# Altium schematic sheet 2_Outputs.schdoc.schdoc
size 309 x 223 mm; Symbol: Sheet-Symbol_A4; Device: Sheet-Symbol_A4; Company: Velizy Astro Club; Drawed: Paul V.; Reviewed: Denis G.; Version: V1.0; Page Size: A4; @Project Name: NAFA AstrAlim; @Page Count: 2; @Update Date: 2024-01-05; @Create Date: 2023-12-28; @Schematic Name: AstrAlim NAFA; Part Number: AstrAlim-v1.0; @Page No: 2; @Page Name: Outputs
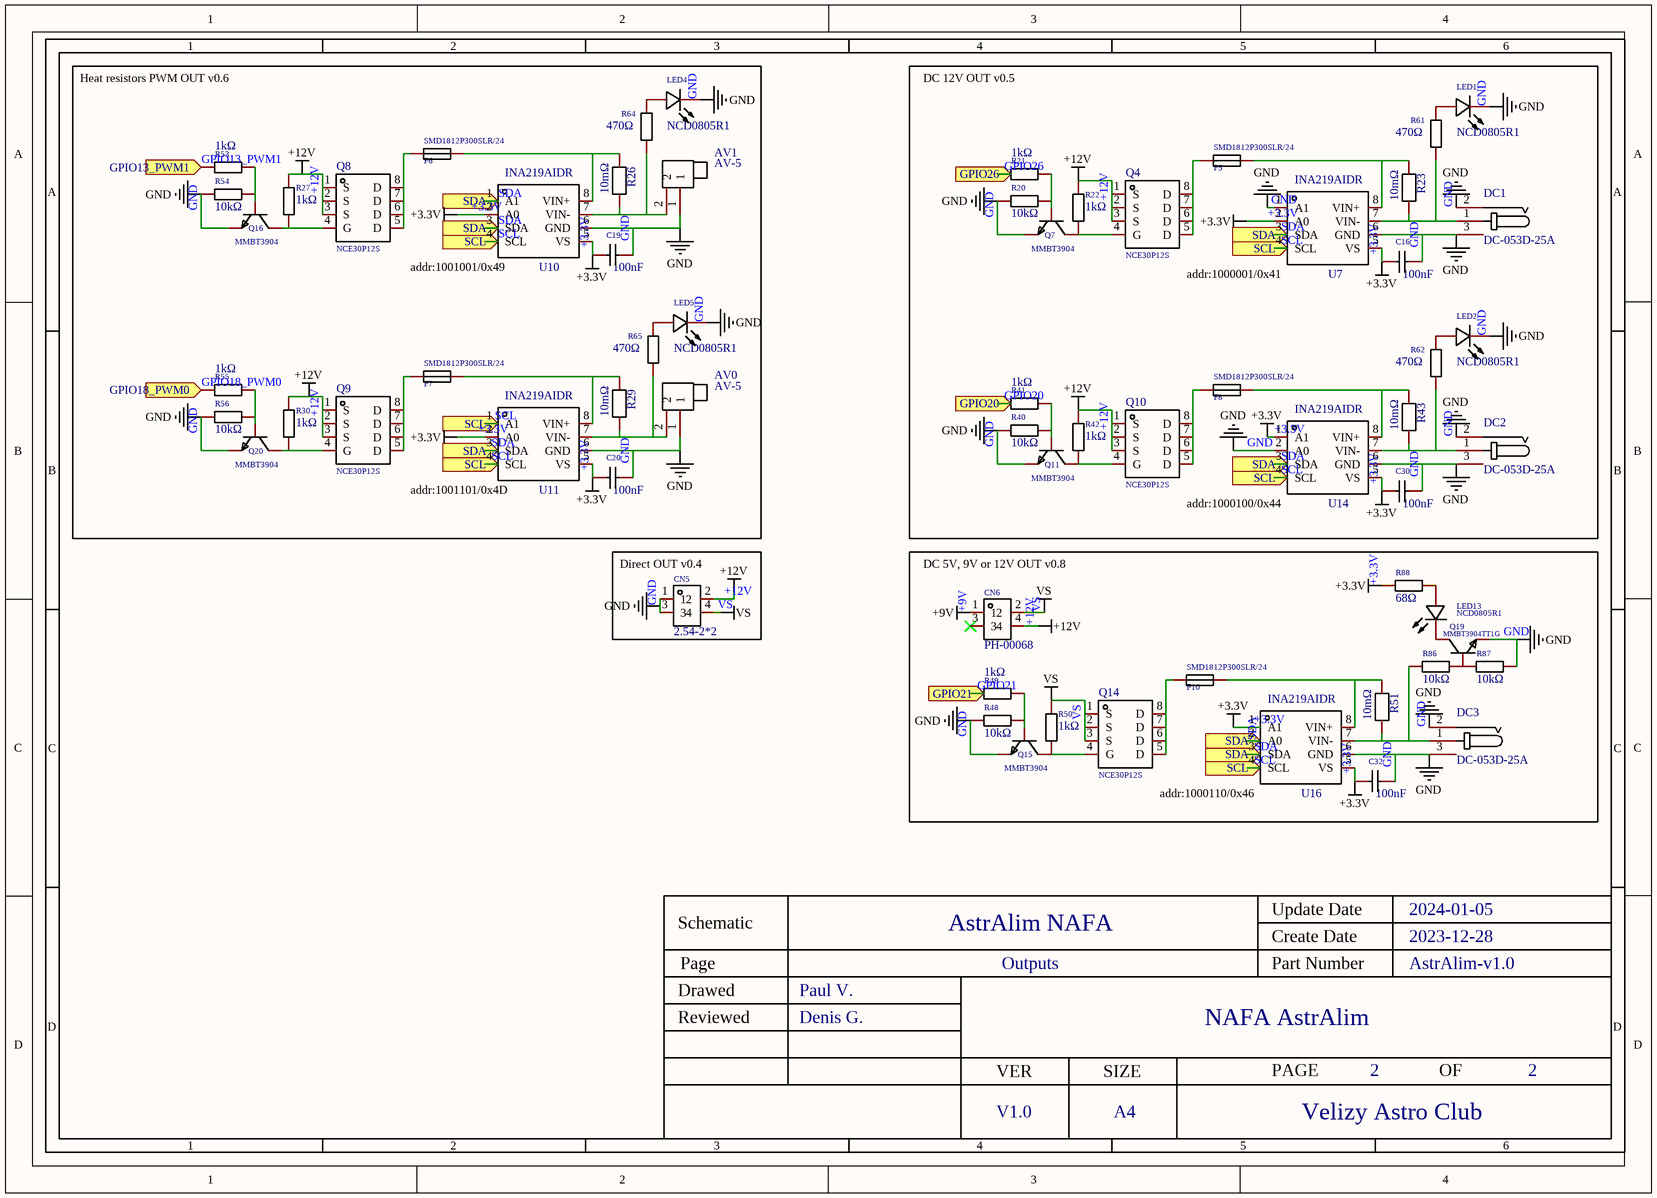
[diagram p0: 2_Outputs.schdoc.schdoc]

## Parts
AV0  AV-5  [CONN-TH_AV-5]
AV1  AV-5  [CONN-TH_AV-5]
C16  100nF  [C0402]
C19  100nF  [C0402]
C20  100nF  [C0402]
C30  100nF  [C0402]
C32  100nF  [C0402]
CN5  2.54-2*2  [HDR-TH_4P-P2.54-V-F-R2-C2-S2.54]
CN6  PH-00068  [HDR-TH_4P-P2.54-V-M-R2-C2-S2.54]
DC1  DC-053D-25A  [DC-IN-TH_DC-053D-25A-1]
DC2  DC-053D-25A  [DC-IN-TH_DC-053D-25A-1]
DC3  DC-053D-25A  [DC-IN-TH_DC-053D-25A-1]
F5  SMD1812P300SLR/24  [F1812]
F6  SMD1812P300SLR/24  [F1812]
F7  SMD1812P300SLR/24  [F1812]
F8  SMD1812P300SLR/24  [F1812]
F10  SMD1812P300SLR/24  [F1812]
LED1  NCD0805R1  [LED0805-R-RD]
LED2  NCD0805R1  [LED0805-R-RD]
LED4  NCD0805R1  [LED0805-R-RD]
LED5  NCD0805R1  [LED0805-R-RD]
LED13  NCD0805R1  [LED0805-R-RD]
Q4  NCE30P12S  [SOIC-8_L4.9-W3.9-P1.27-LS6.0-BL]
Q7  MMBT3904  [SOT-23-3_L2.9-W1.3-P1.90-LS2.4-BR]
Q8  NCE30P12S  [SOIC-8_L4.9-W3.9-P1.27-LS6.0-BL]
Q9  NCE30P12S  [SOIC-8_L4.9-W3.9-P1.27-LS6.0-BL]
Q10  NCE30P12S  [SOIC-8_L4.9-W3.9-P1.27-LS6.0-BL]
Q11  MMBT3904  [SOT-23-3_L2.9-W1.3-P1.90-LS2.4-BR]
Q14  NCE30P12S  [SOIC-8_L4.9-W3.9-P1.27-LS6.0-BL]
Q15  MMBT3904  [SOT-23-3_L2.9-W1.3-P1.90-LS2.4-BR]
Q16  MMBT3904  [SOT-23-3_L2.9-W1.3-P1.90-LS2.4-BR]
Q19  MMBT3904TT1G  [SC-75-3_L1.6-W0.8-P1.00-LS1.6-BR]
Q20  MMBT3904  [SOT-23-3_L2.9-W1.3-P1.90-LS2.4-BR]
R20  10kΩ  [R0402]
R21  1kΩ  [R0402]
R22  1kΩ  [R0402]
R23  10mΩ  [R1206]
R26  10mΩ  [R1206]
R27  1kΩ  [R0402]
R29  10mΩ  [R1206]
R30  1kΩ  [R0402]
R40  10kΩ  [R0402]
R41  1kΩ  [R0402]
R42  1kΩ  [R0402]
R43  10mΩ  [R1206]
R48  10kΩ  [R0402]
R49  1kΩ  [R0402]
R50  1kΩ  [R0402]
R51  10mΩ  [R1206]
R53  1kΩ  [R0402]
R54  10kΩ  [R0402]
R55  1kΩ  [R0402]
R56  10kΩ  [R0402]
R61  470Ω  [R0402]
R62  470Ω  [R0402]
R64  470Ω  [R0402]
R65  470Ω  [R0402]
R86  10kΩ  [R0402]
R87  10kΩ  [R0402]
R88  68Ω  [R0603]
U7  INA219AIDR  [SOIC-8_L4.9-W3.9-P1.27-LS6.0-BL]
U10  INA219AIDR  [SOIC-8_L4.9-W3.9-P1.27-LS6.0-BL]
U11  INA219AIDR  [SOIC-8_L4.9-W3.9-P1.27-LS6.0-BL]
U14  INA219AIDR  [SOIC-8_L4.9-W3.9-P1.27-LS6.0-BL]
U16  INA219AIDR  [SOIC-8_L4.9-W3.9-P1.27-LS6.0-BL]

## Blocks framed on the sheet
Direct OUT v0.4: CN5

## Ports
GPIO13_PWM1 (in), GPIO18_PWM0 (in), GPIO20 (in), GPIO21 (in), GPIO26 (in), SCL (in), SDA (in)

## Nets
+3.3V: C16.1 C19.1 C20.1 C30.1 C32.1 R88.1 U7.2(A0) U7.5(VS) U10.2(A0) U10.5(VS) U11.2(A0) U11.5(VS) U14.1(A1) U14.5(VS) U16.1(A1) U16.5(VS)
+9V: CN6.1
+12V: CN5.2 CN6.4 Q4.1(S) Q4.2(S) Q4.3(S) Q8.1(S) Q8.2(S) Q8.3(S) Q9.1(S) Q9.2(S) Q9.3(S) Q10.1(S) Q10.2(S) Q10.3(S) R22.2 R27.2 R30.2 R42.2
GND: AV0.1 AV1.1 C16.2 C19.2 C20.2 C30.2 C32.2 CN5.1 CN5.3 DC1.2 DC1.3 DC2.2 DC2.3 DC3.2 DC3.3 LED1.2(-) LED2.2(-) LED4.2(-) LED5.2(-) Q7.2(E) Q11.2(E) Q15.2(E) Q16.2(E) Q19.2(E) Q20.2(E) R20.1 R40.1 R48.1 R54.1 R56.1 R87.1 U7.1(A1) U7.6(GND) U10.6(GND) U11.6(GND) U14.2(A0) U14.6(GND) U16.6(GND)
VS: CN5.4 CN6.2 Q14.1(S) Q14.2(S) Q14.3(S) R50.2
GPIO13_PWM1: R53.1 ; port GPIO13_PWM1
GPIO18_PWM0: R55.1 ; port GPIO18_PWM0
GPIO20: R41.1 ; port GPIO20
GPIO21: R49.1 ; port GPIO21
GPIO26: R21.1 ; port GPIO26
SCL: U7.4(SCL) U10.4(SCL) U11.1(A1) U11.4(SCL) U14.4(SCL) U16.4(SCL) ; port SCL
SDA: U7.3(SDA) U10.1(A1) U10.3(SDA) U11.3(SDA) U14.3(SDA) U16.2(A0) U16.3(SDA) ; port SDA
NetAV0_2: AV0.2 R29.1 R65.1 U11.7(VIN-)
NetAV1_2: AV1.2 R26.1 R64.1 U10.7(VIN-)
NetDC1_1: DC1.1 R23.1 R61.1 U7.7(VIN-)
NetDC2_1: DC2.1 R43.1 R62.1 U14.7(VIN-)
NetDC3_1: DC3.1 R51.1 R86.2 U16.7(VIN-)
NetF5_1: F5.1 R23.2 U7.8(VIN+)
NetF5_2: F5.2 Q4.5(D) Q4.6(D) Q4.7(D) Q4.8(D)
NetF6_1: F6.1 R26.2 U10.8(VIN+)
NetF6_2: F6.2 Q8.5(D) Q8.6(D) Q8.7(D) Q8.8(D)
NetF7_1: F7.1 R29.2 U11.8(VIN+)
NetF7_2: F7.2 Q9.5(D) Q9.6(D) Q9.7(D) Q9.8(D)
NetF8_1: F8.1 R43.2 U14.8(VIN+)
NetF8_2: F8.2 Q10.5(D) Q10.6(D) Q10.7(D) Q10.8(D)
NetF10_1: F10.1 R51.2 U16.8(VIN+)
NetF10_2: F10.2 Q14.5(D) Q14.6(D) Q14.7(D) Q14.8(D)
NetLED1_1: LED1.1(+) R61.2
NetLED2_1: LED2.1(+) R62.2
NetLED4_1: LED4.1(+) R64.2
NetLED5_1: LED5.1(+) R65.2
NetLED13_1: LED13.1(+) R88.2
NetLED13_2: LED13.2(-) Q19.3(C)
NetQ4_4: Q4.4(G) Q7.3(C) R22.1
NetQ7_1: Q7.1(B) R20.2 R21.2
NetQ8_4: Q8.4(G) Q16.3(C) R27.1
NetQ9_4: Q9.4(G) Q20.3(C) R30.1
NetQ10_4: Q10.4(G) Q11.3(C) R42.1
NetQ11_1: Q11.1(B) R40.2 R41.2
NetQ14_4: Q14.4(G) Q15.3(C) R50.1
NetQ15_1: Q15.1(B) R48.2 R49.2
NetQ16_1: Q16.1(B) R53.2 R54.2
NetQ19_1: Q19.1(B) R86.1 R87.2
NetQ20_1: Q20.1(B) R55.2 R56.2

Not connected (* = marked no-connect by the designer): CN6 3*

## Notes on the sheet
- Heat resistors PWM OUT v0.6
- DC 12V OUT v0.5
- (near U10) addr:1001001/0x49
- addr:1000001/0x41
- (near U11) addr:1001101/0x4D
- addr:1000100/0x44
- (near CN6) DC 5V, 9V or 12V OUT v0.8
- addr:1000110/0x46

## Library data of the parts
AV0 AV1 = AV-5: Connector Type:3.5mm耳机座 Current Rating (Max):- Voltage Rating (Max):- Operating Temperature Range:- Operating Temperature Range:-; Manufacturer: BOOMELE(博穆精密); Add into BOM: yes
C16 C19 C20 C30 C32 = CL05B104KO5NNNC: Capacitance: Tolerance:±10% Tolerance:±10% Voltage Rated: Temperature Coefficient:; Manufacturer: SAMSUNG(三星); Add into BOM: yes; Tolerance: ±10%
CN5 = 2.54-2*2: Number of Rows:双排 Number of Holes:4P Pitch:2.54mm Holes Structure:2x2P Row Spacing:2.54mm Mounting Type:Straight Circular Hole / Square Hole:Square Holes Current Rating (Max):2.5A Voltage Rating (Max):- Holes Direction:Top Insulation Height:8.5mm Operatin; Manufacturer: ZHOURI(洲日); Add into BOM: yes; Number of Holes: 4P; Pitch: 2.54mm; Holes Structure: 2x2P; Current Rating (Max): 2.5A; Holes Direction: Top
CN6 = PH-00068: Pin Structure:2x2P Pitch:2.54mm Number of Pins:4P Mounting Type:Straight Number of Rows:双排 Row Spacing:2.54mm Circluar Pins/Square Pins:Square Pins Current Rating (Max):3A Voltage Rating (Max):- Length of Mating Pin:6mm Insulation Height:2.5mm Length of E; Manufacturer: Liansheng(连盛); Add into BOM: yes; Pin Structure: 2x2P; Pitch: 2.54mm; Current Rating (Max): 3A
DC1-DC3 = DC-053D-25A: Connector Type:DC Power Receptacle Mounting Style:Shrouded Inside Contact Diameter:2.5mm Outside Contact Diameter:6.5mm Current Rating (Max):10A Voltage Rating (Max):16V Operating Temperature Range:-20℃~+70℃ Operating Temperature Range:-20℃~+70℃; Manufacturer: 韩国韩荣; Add into BOM: yes; Inside Contact Diameter: 2.5mm; Outside Contact Diameter: 6.5mm; Current Rating (Max): 10A; Voltage Rating (Max): 16V
F5-F8 F10 = SMD1812P300SLR/24_C2892380: Operating Voltage (Max):24V Current Rating (Max):50A Hold Current:3A Trip Current:6A Power Dissipation:2W Resistance - Initial (Ri) (Min):0.001Ω Resistance - Post Trip (R1) (Max):0.03Ω Maximum Time to Trip:2s Operating Temperature:-40℃~+85℃ Operating Temp; Manufacturer: PTTC(聚鼎); Add into BOM: yes; Operating Voltage (Max): 24V; Current Rating (Max): 50A; Hold Current: 3A; Trip Current: 6A; Power Dissipation: 2W; Resistance - Initial (Ri) (Min): 0.001Ω; Resistance - Post Trip (R1) (Max): 0.03Ω; Maximum Time to Trip: 2s
LED1 LED2 LED4 LED5 LED13 = NCD0805R1_C84256: Emitted Color:Red Diode Configuration:- Lamp Holder Type:- Forward Voltage (VF):1.6V~2.6V Forward Voltage (VF):1.6V~2.6V Forward Current:20mA Power Dissipation:65mW Lens Color:无色透明 Dominant Wavelength:615nm~630nm Dominant Wavelength:615nm~630nm Peak Wavel; Manufacturer: 国星光电; Symbol: FC-2012HRK-620D; Add into BOM: yes; Emitted Color: Red; Forward Current: 20mA; Power Dissipation: 65mW; Lens Color: 无色透明; Luminous Intensity: 67mcd~195mcd; Viewing Angle: 130°
Q4 Q8-Q10 Q14 = NCE30P12S: Type: Drain Source Voltage (Vdss): Continuous Drain Current (Id): Power Dissipation (Pd): Drain Source On Resistance (RDS(on)@Vgs,Id):15mΩ@10V,10A Gate Threshold Voltage (Vgs(th)@Id):3V@250uA; Manufacturer: NCE(无锡新洁能); Add into BOM: yes
Q7 Q11 Q15 Q16 Q20 = MMBT3904_C20526: Transistor Type: Collector Current (Ic): Collector-Emitter Breakdown Voltage (Vceo): Power Dissipation (Pd): DC Current Gain (hFE@Ic,Vce):100@10mA,1V DC Current Gain (hFE@Ic,Vce):100@10mA,1V Transition Frequency (fT):300MHz Collector Cut-Off Current (Icbo; Manufacturer: CJ(江苏长电/长晶); Add into BOM: yes; Transition Frequency (fT): 300MHz; Collector Cut-Off Current (Icbo): 100nA; Collector-Emitter Saturation Voltage (VCE(sat)@Ic,Ib): 300mV@50mA,5mA
Q19 = MMBT3904TT1G: Transistor Type: Collector Current (Ic): Collector-Emitter Breakdown Voltage (Vceo): Power Dissipation (Pd): DC Current Gain (hFE@Ic,Vce):100@10mA,1V DC Current Gain (hFE@Ic,Vce):100@10mA,1V Transition Frequency (fT):300MHz Collector-Emitter Saturation Vo; Manufacturer: onsemi(安森美); Add into BOM: yes; Transition Frequency (fT): 300MHz; Collector-Emitter Saturation Voltage (VCE(sat)@Ic,Ib): 300mV@5mA,50mA
R20 R40 R48 R54 R56 R86 R87 = 0402WGF1002TCE: Resistance:10000Ω Tolerance:±1% Tolerance:±1% Power(Watts): Overload Voltage (Max): Temperature Coefficient:±100ppm/℃ Temperature Coefficient:±100ppm/℃ Type:Thick Film Resistors Operating Temperature Range:-55℃~+155℃ Operating Temperature Range:-55℃~+155℃; Manufacturer: UNI-ROYAL(厚声); Add into BOM: yes; Tolerance: ±1%
R21 R22 R27 R30 R41 R42 R49 R50 R53 R55 = 0402WGF1001TCE: Resistance:1000Ω Tolerance:±1% Tolerance:±1% Power(Watts): Overload Voltage (Max): Temperature Coefficient:±100ppm/℃ Temperature Coefficient:±100ppm/℃ Type:Thick Film Resistors Operating Temperature Range:-55℃~+155℃ Operating Temperature Range:-55℃~+155℃; Manufacturer: UNI-ROYAL(厚声); Add into BOM: yes; Tolerance: ±1%
R23 R26 R29 R43 R51 = MFJ06HR010FT: Resistance:10mΩ Tolerance:±1% Tolerance:±1% Power(Watts): Temperature Coefficient:±50ppm/℃ Temperature Coefficient:±50ppm/℃ Overload Voltage (Max):- Operating Temperature Range:-55℃~+170℃ Operating Temperature Range:-55℃~+170℃; Manufacturer: FH(风华); Add into BOM: yes; Tolerance: ±1%
R61 R62 R64 R65 = 0402WGF4700TCE: Resistance: Tolerance:±1% Tolerance:±1% Power(Watts): Overload Voltage (Max): Temperature Coefficient:±100ppm/℃ Temperature Coefficient:±100ppm/℃ Type:Thick Film Resistors Operating Temperature Range:-55℃~+155℃ Operating Temperature Range:-55℃~+155℃; Manufacturer: UNI-ROYAL(厚声); Add into BOM: yes; Tolerance: ±1%
R88 = 0603WAF680JT5E: Resistance:68000mΩ Tolerance:±1% Tolerance:±1% Power(Watts): Overload Voltage (Max): Temperature Coefficient:±100ppm/℃ Temperature Coefficient:±100ppm/℃ Type:Thick Film Resistors Operating Temperature Range:-55℃~+155℃ Operating Temperature Range:-55℃~+155; Manufacturer: UNI-ROYAL(厚声); Add into BOM: yes; Tolerance: ±1%
U7 U10 U11 U14 U16 = INA219AIDR: Manufacturer: TI(德州仪器); Add into BOM: yes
